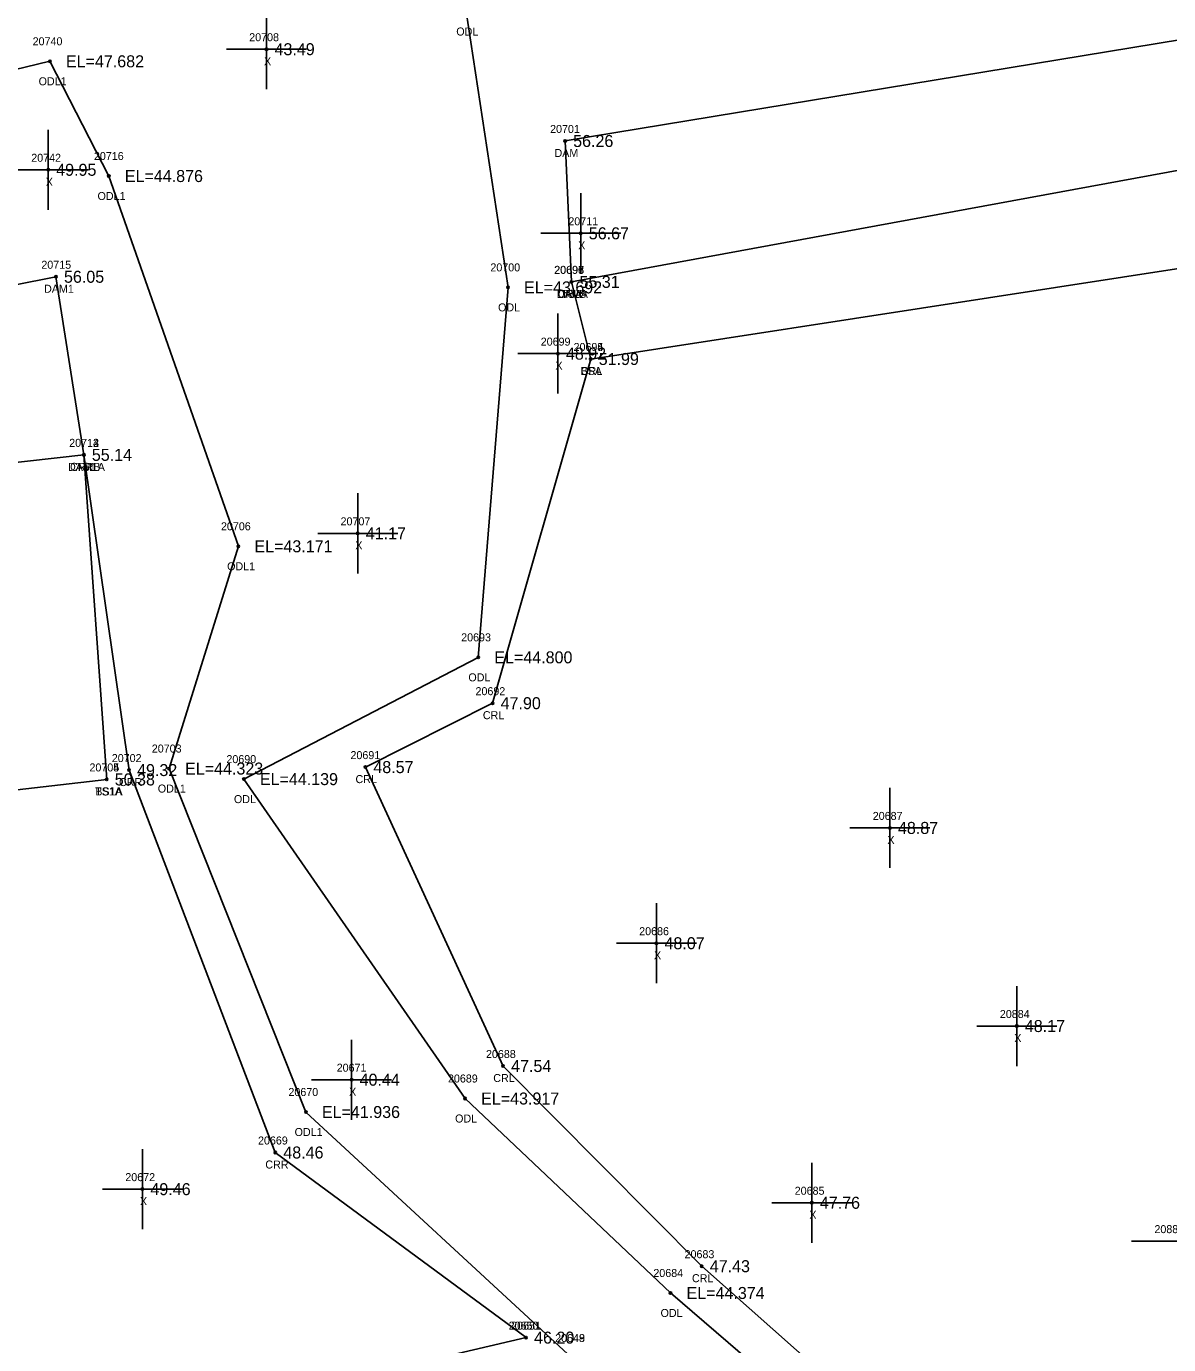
# Model space of a CAD drawing. Extents: x 2420351 to 2422725, y 845330 to 846558.
# Drawn here: x 2421635.3 to 2421778.1, y 845866.8 to 846031.6 of the extents above; entities that cross this region are included whole.
import ezdxf

# ---------------------------------------------------------------- set-up
doc = ezdxf.new("R2010")
doc.units = 0
for name, color, linetype in [('RD_DTM_BkLn2', 7, 'Continuous'), ('RD_DTM_BkLn_txCode', 7, 'Continuous'), ('RD_EX_Dam', 7, 'Continuous'), ('RD_EX_Dam_txCode', 7, 'Continuous'), ('RD_EX_H2O', 7, 'Continuous'), ('RD_EX_H2O_txCode', 7, 'Continuous'), ('RD_EX_Misc', 7, 'Continuous'), ('RD_EX_Misc_txCode', 7, 'Continuous'), ('RD_EX_TX_Dam_ELEV', 7, 'Continuous'), ('RD_EX_TX_H2O_ELEV', 7, 'Continuous'), ('RD_EX_TX_Misc_ELEV', 7, 'Continuous'), ('RD_SMD_Locator', 7, 'Continuous')]:
    doc.layers.add(name, color=color, linetype=linetype)

msp = doc.modelspace()

# ---------------------------------------------------------------- linework, layer by layer
at = {"layer": 'RD_DTM_BkLn2'}
for points in [[(2421703.45, 845999.67), (2421800.66, 846017.53), (2421880.42, 846035.1), (2421923.1, 846041.94), (2421954.1, 846046.17), (2421954.1, 846046.17), (2422030.99, 846060.95), (2422065.43, 846069.36), (2422120.97, 846103.75), (2422145.48, 846129.05), (2422185.42, 846182.09)], [(2421705.85, 845990.03), (2421805.22, 846005.36), (2421884.52, 846023.82), (2421952.92, 846021.64)], [(2421645.39, 845937.48), (2421557.48, 845927.33), (2421481.26, 845936.58), (2421470.04, 845970.14), (2421488.91, 845998.31)], [(2421645.39, 845937.48), (2421642.53, 845978.05), (2421578.04, 845970.81), (2421533.18, 845959.97), (2421503.44, 845954.37)]]:
    msp.add_lwpolyline(points, dxfattribs=at)
at = {"layer": 'RD_EX_Dam'}
for points in [[(2421703.45, 845999.67), (2421702.66, 846017.28), (2421795.13, 846032.49), (2421876.44, 846046.05), (2421920.78, 846055.77), (2422010.13, 846069.83), (2422010.13, 846069.83), (2422059.48, 846081.4), (2422106.12, 846132.59), (2422121.56, 846164.68), (2422122.27, 846182.92)], [(2421642.53, 845978.05), (2421639.05, 846000.31), (2421580.85, 845988.77), (2421535.07, 845982.51), (2421515.21, 845982.5), (2421497.5, 845976.94), (2421503.44, 845954.37)]]:
    msp.add_lwpolyline(points, dxfattribs=at)
at = {"layer": 'RD_EX_H2O'}
for points in [[(2421769.97, 845784.59), (2421757.53, 845787.6), (2421742.96, 845811.73), (2421745.62, 845824.92), (2421731.55, 845840.59), (2421714.37, 845860.98), (2421703.55, 845865.16), (2421670.27, 845895.91), (2421653.18, 845938.84), (2421661.84, 845966.62), (2421645.65, 846012.9), (2421638.29, 846027.24), (2421576.72, 846012.28), (2421545.4, 846011.31), (2421531.8, 846021.91), (2421540.87, 846056.88), (2421568.83, 846092.43), (2421605.18, 846118.43)], [(2421789.64, 845837.83), (2421782.25, 845842.65), (2421762.14, 845838.6), (2421745.54, 845847.69), (2421715.82, 845873.29), (2421690.16, 845897.6), (2421662.52, 845937.52), (2421691.81, 845952.74), (2421695.52, 845998.98), (2421690.3, 846033.46), (2421790.46, 846058.61), (2421873.55, 846071.45), (2421916.6, 846080.01)], [(2421697.78, 845867.71), (2421684.61, 845864.63), (2421657.29, 845855.17), (2421611.89, 845870.76), (2421583.33, 845881.87), (2421549.84, 845871.2), (2421517.26, 845862.24), (2421475.01, 845867.75), (2421422.24, 845899.02), (2421422.38, 845924.44), (2421434.43, 845964.2), (2421465.61, 845987.89), (2421488.91, 845998.31), (2421509.34, 846009.28), (2421510.99, 846011.42)], [(2421803.88, 845842.86), (2421794.61, 845845.35), (2421789.35, 845845.31), (2421784.3, 845849.6), (2421763.68, 845842.08), (2421749.32, 845850.38), (2421719.73, 845876.64), (2421694.91, 845901.66), (2421677.7, 845939.02), (2421693.6, 845947.01), (2421705.85, 845990.03), (2421703.45, 845999.67)], [(2421697.78, 845867.71), (2421666.45, 845890.85), (2421648.18, 845938.65), (2421642.53, 845978.05)]]:
    msp.add_lwpolyline(points, dxfattribs=at)
at = {"layer": 'RD_EX_Misc'}
for p, q in [((2421665.35, 846023.75), (2421665.35, 846033.75)), ((2421660.35, 846028.75), (2421670.35, 846028.75)), ((2421638.08, 846008.68), (2421638.08, 846018.68)), ((2421633.08, 846013.68), (2421643.08, 846013.68)), ((2421704.61, 846000.74), (2421704.61, 846010.74)), ((2421699.61, 846005.74), (2421709.61, 846005.74)), ((2421701.76, 845985.7), (2421701.76, 845995.7)), ((2421696.76, 845990.7), (2421706.76, 845990.7)), ((2421676.75, 845963.24), (2421676.75, 845973.24)), ((2421671.75, 845968.24), (2421681.75, 845968.24)), ((2421743.24, 845926.42), (2421743.24, 845936.42)), ((2421738.24, 845931.42), (2421748.24, 845931.42)), ((2421714.07, 845912.01), (2421714.07, 845922.01)), ((2421709.07, 845917.01), (2421719.07, 845917.01)), ((2421759.09, 845901.66), (2421759.09, 845911.66)), ((2421754.09, 845906.66), (2421764.09, 845906.66)), ((2421675.98, 845894.95), (2421675.98, 845904.95)), ((2421670.98, 845899.95), (2421680.98, 845899.95)), ((2421649.85, 845881.27), (2421649.85, 845891.27)), ((2421733.48, 845879.57), (2421733.48, 845889.57)), ((2421644.85, 845886.27), (2421654.85, 845886.27)), ((2421728.48, 845884.57), (2421738.48, 845884.57)), ((2421773.4, 845879.77), (2421783.4, 845879.77))]:
    msp.add_line(p, q, dxfattribs=at)
at = {"layer": 'RD_SMD_Locator'}
for centre in [(2421665.35, 846028.75), (2421638.29, 846027.24), (2421702.66, 846017.28), (2421638.08, 846013.68), (2421645.65, 846012.9), (2421704.61, 846005.74), (2421639.05, 846000.31), (2421703.45, 845999.67), (2421703.45, 845999.67), (2421703.45, 845999.67), (2421695.52, 845998.98), (2421701.76, 845990.7), (2421705.85, 845990.03), (2421705.85, 845990.03), (2421642.53, 845978.05), (2421642.53, 845978.05), (2421642.53, 845978.05), (2421676.75, 845968.24), (2421661.84, 845966.62), (2421691.81, 845952.74), (2421693.6, 845947.01), (2421648.18, 845938.65), (2421653.18, 845938.84), (2421677.7, 845939.02), (2421645.39, 845937.48), (2421645.39, 845937.48), (2421662.52, 845937.52), (2421743.24, 845931.42), (2421714.07, 845917.01), (2421759.09, 845906.66), (2421694.91, 845901.66), (2421675.98, 845899.95), (2421690.16, 845897.6), (2421670.27, 845895.91), (2421666.45, 845890.85), (2421649.85, 845886.27), (2421733.48, 845884.57), (2421719.73, 845876.64), (2421715.82, 845873.29), (2421697.78, 845867.71), (2421697.78, 845867.71)]:
    msp.add_circle(centre, 0.15, dxfattribs=at)

# ---------------------------------------------------------------- texts
at = {"layer": 'RD_DTM_BkLn_txCode'}
for s, p in [('20697', (2421701.31, 846000.67)), ('TSA', (2421702.17, 845997.67)), ('20694', (2421703.71, 845991.03)), ('BSA', (2421704.58, 845988.03)), ('20713', (2421640.7, 845979.05)), ('TS1', (2421641.57, 845976.05)), ('20704', (2421643.23, 845938.48)), ('20705', (2421643.23, 845938.48)), ('TS1A', (2421643.94, 845935.48)), ('BS1A', (2421643.96, 845935.48))]:
    msp.add_text(s, height=1, dxfattribs=at).set_placement(p)
at = {"layer": 'RD_EX_Dam_txCode'}
for s, p in [('20701', (2421700.78, 846018.28)), ('DAM', (2421701.33, 846015.28)), ('20715', (2421637.22, 846001.31)), ('20698', (2421701.31, 846000.67)), ('DAM1', (2421637.56, 845998.31)), ('DAMA', (2421701.63, 845997.67)), ('20714', (2421640.7, 845979.05)), ('DAM1A', (2421640.55, 845976.05))]:
    msp.add_text(s, height=1, dxfattribs=at).set_placement(p)
at = {"layer": 'RD_EX_H2O_txCode'}
for s, p in [('ODL', (2421689.06, 846030.46)), ('20740', (2421636.13, 846029.24)), ('ODL1', (2421636.88, 846024.24)), ('20716', (2421643.79, 846014.9)), ('ODL1', (2421644.24, 846009.9)), ('20700', (2421693.32, 846000.98)), ('20696', (2421701.28, 846000.67)), ('CRLB', (2421701.75, 845997.67)), ('ODL', (2421694.28, 845995.98)), ('20695', (2421703.71, 845991.03)), ('CRL', (2421704.62, 845988.03)), ('20712', (2421640.7, 845979.05)), ('CRRB', (2421640.81, 845976.05)), ('20706', (2421659.66, 845968.62)), ('ODL1', (2421660.43, 845963.62)), ('20693', (2421689.67, 845954.74)), ('ODL', (2421690.57, 845949.74)), ('20692', (2421691.46, 845948.01)), ('CRL', (2421692.38, 845945.01)), ('20703', (2421651.02, 845940.84)), ('20702', (2421646.02, 845939.65)), ('20690', (2421660.34, 845939.52)), ('20691', (2421675.84, 845940.02)), ('CRR', (2421646.93, 845936.65)), ('ODL1', (2421651.77, 845935.84)), ('CRL', (2421676.47, 845937.02)), ('ODL', (2421661.28, 845934.52)), ('20688', (2421692.77, 845902.66)), ('20689', (2421688.02, 845899.6)), ('CRL', (2421693.68, 845899.66)), ('20670', (2421668.09, 845897.91)), ('ODL', (2421688.91, 845894.6)), ('ODL1', (2421668.86, 845892.91)), ('20669', (2421664.29, 845891.85)), ('CRR', (2421665.2, 845888.85)), ('20683', (2421717.58, 845877.64)), ('20684', (2421713.68, 845875.29)), ('CRL', (2421718.5, 845874.64)), ('ODL', (2421714.58, 845870.29)), ('20650', (2421695.6, 845868.71)), ('20651', (2421695.92, 845868.71)), ('20648', (2421701.41, 845867.16)), ('20649', (2421701.41, 845867.16))]:
    msp.add_text(s, height=1, dxfattribs=at).set_placement(p)
at = {"layer": 'RD_EX_Misc_txCode'}
for s, p in [('20708', (2421663.19, 846029.75)), ('X', (2421665.04, 846026.75)), ('20742', (2421635.96, 846014.68)), ('X', (2421637.77, 846011.68)), ('20711', (2421703.06, 846006.74)), ('X', (2421704.29, 846003.74)), ('20699', (2421699.61, 845991.7)), ('X', (2421701.44, 845988.7)), ('20707', (2421674.6, 845969.24)), ('X', (2421676.44, 845966.24)), ('20687', (2421741.09, 845932.42)), ('X', (2421742.92, 845929.42)), ('20686', (2421711.91, 845918.01)), ('X', (2421713.76, 845915.01)), ('20884', (2421756.97, 845907.66)), ('X', (2421758.77, 845904.66)), ('20671', (2421674.12, 845900.95)), ('X', (2421675.67, 845897.95)), ('20672', (2421647.71, 845887.27)), ('20685', (2421731.34, 845885.57)), ('X', (2421649.54, 845884.27)), ('X', (2421733.17, 845882.57)), ('20883', (2421776.28, 845880.77))]:
    msp.add_text(s, height=1, dxfattribs=at).set_placement(p)
at = {"layer": 'RD_EX_TX_Dam_ELEV'}
for s, p in [('56.26', (2421703.66, 846016.53)), ('56.05', (2421640.05, 845999.56)), ('55.31', (2421704.45, 845998.92)), ('55.14', (2421643.53, 845977.3))]:
    msp.add_text(s, height=1.5, dxfattribs=at).set_placement(p)
at = {"layer": 'RD_EX_TX_H2O_ELEV'}
for s, p in [('EL=47.682', (2421640.29, 846026.49)), ('EL=44.876', (2421647.65, 846012.15)), ('EL=43.692', (2421697.52, 845998.23)), ('55.31', (2421704.45, 845998.92)), ('51.99', (2421706.85, 845989.28)), ('55.14', (2421643.53, 845977.3)), ('EL=43.171', (2421663.84, 845965.87)), ('EL=44.800', (2421693.81, 845951.99)), ('47.90', (2421694.6, 845946.26)), ('49.32', (2421649.18, 845937.9)), ('EL=44.323', (2421655.18, 845938.09)), ('EL=44.139', (2421664.52, 845936.77)), ('48.57', (2421678.7, 845938.27)), ('47.54', (2421695.91, 845900.91)), ('EL=43.917', (2421692.16, 845896.85)), ('EL=41.936', (2421672.27, 845895.16)), ('48.46', (2421667.45, 845890.1)), ('47.43', (2421720.73, 845875.89)), ('EL=44.374', (2421717.82, 845872.54)), ('46.20', (2421698.78, 845866.96)), ('46.20', (2421698.78, 845866.96))]:
    msp.add_text(s, height=1.5, dxfattribs=at).set_placement(p)
at = {"layer": 'RD_EX_TX_Misc_ELEV'}
for s, p in [('43.49', (2421666.35, 846028)), ('49.95', (2421639.08, 846012.93)), ('56.67', (2421705.61, 846004.99)), ('55.31', (2421704.45, 845998.92)), ('48.92', (2421702.76, 845989.95)), ('51.99', (2421706.85, 845989.28)), ('55.14', (2421643.53, 845977.3)), ('41.17', (2421677.75, 845967.49)), ('50.38', (2421646.39, 845936.73)), ('50.38', (2421646.39, 845936.73)), ('48.87', (2421744.24, 845930.67)), ('48.07', (2421715.07, 845916.26)), ('48.17', (2421760.09, 845905.91)), ('40.44', (2421676.98, 845899.2)), ('49.46', (2421650.85, 845885.52)), ('47.76', (2421734.48, 845883.82))]:
    msp.add_text(s, height=1.5, dxfattribs=at).set_placement(p)

doc.saveas('drawing.dxf')
